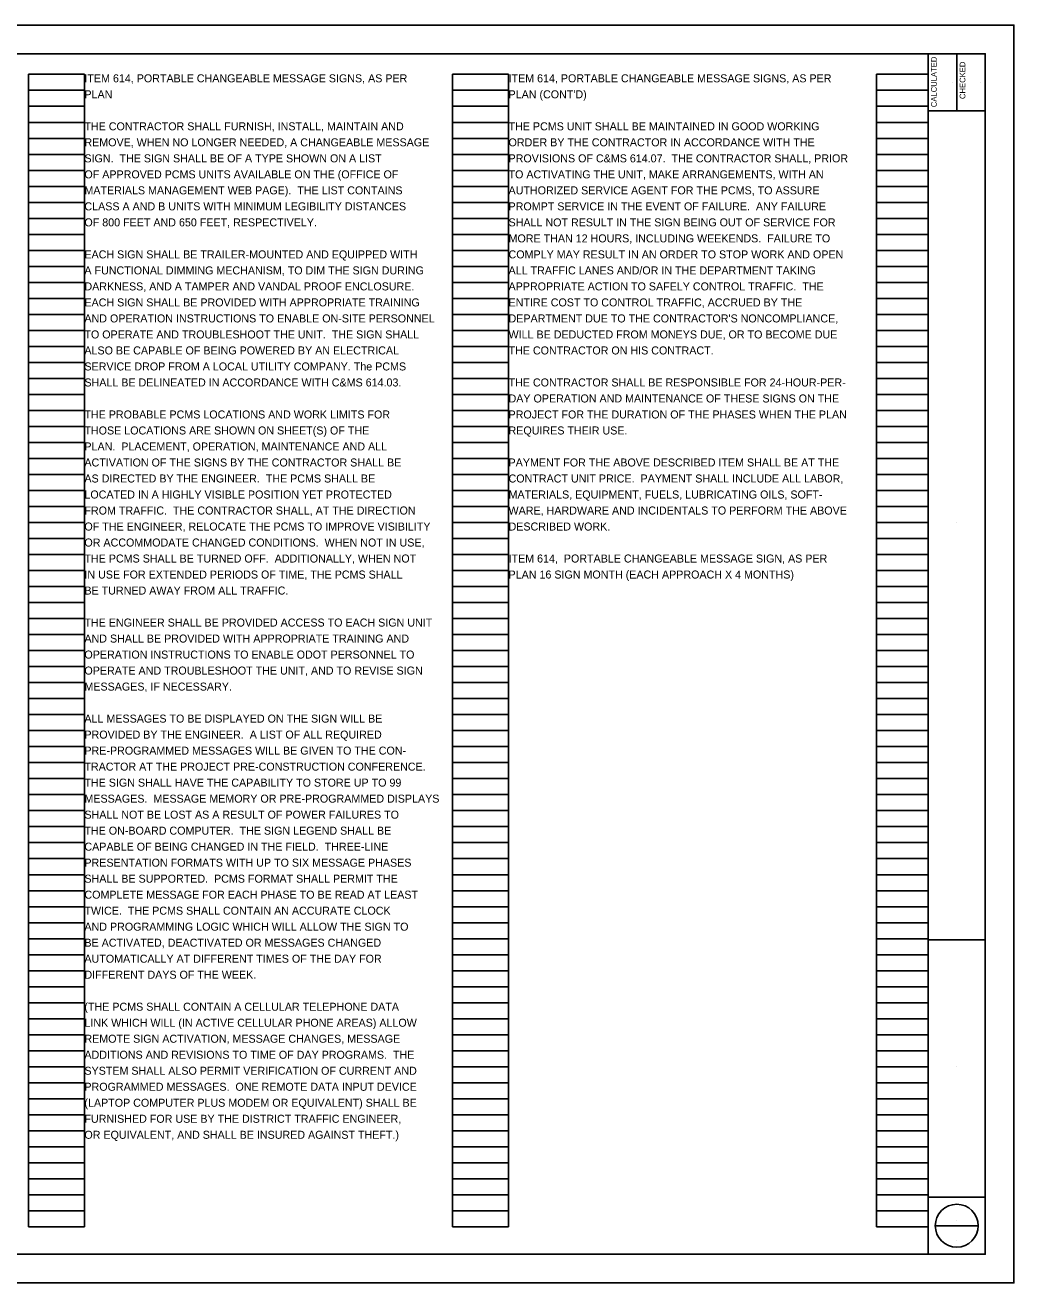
# Model space of a CAD drawing. Extents: x 0 to 71.8, y 0 to 22.
# Drawn here: x 16.7 to 34, y 0 to 22 of the extents above; entities that cross this region are included whole.
import ezdxf

# ---------------------------------------------------------------- set-up
doc = ezdxf.new("R2010")
doc.units = 0
for name, color, linetype in [('MT_P_Work_Area', 7, 'Continuous'), ('SH_Cut_Line', 7, 'Continuous'), ('SH_Data', 7, 'Continuous'), ('SH_Text', 7, 'Continuous')]:
    doc.layers.add(name, color=color, linetype=linetype)

msp = doc.modelspace()

# ---------------------------------------------------------------- linework, layer by layer
at = {"layer": 'MT_P_Work_Area'}
for p, q in [((32.5, 0.5), (32.5, 21.5)), ((33, 21.5), (33, 20.5)), ((32.5, 20.5), (33.5, 20.5)), ((32.5, 6), (33.5, 6)), ((32.5, 1.5), (33.5, 1.5))]:
    msp.add_line(p, q, dxfattribs=at)
msp.add_lwpolyline([(2, 21.5), (33.5, 21.5), (33.5, 0.5), (2, 0.5)], close=True, dxfattribs=at)
at = {"layer": 'SH_Cut_Line'}
msp.add_lwpolyline([(0, 0), (34, 0), (34, 22), (0, 22)], close=True, dxfattribs=at)
at = {"layer": 'SH_Data'}
for p, q in [((16.76, 0.98), (16.76, 21.14)), ((16.76, 21.14), (17.74, 21.14)), ((17.74, 0.98), (17.74, 21.14)), ((24.18, 0.98), (24.18, 21.14)), ((24.18, 21.14), (25.16, 21.14)), ((25.16, 0.98), (25.16, 21.14)), ((31.6, 0.98), (31.6, 21.14)), ((31.6, 21.14), (32.5, 21.14)), ((32.5, 0.98), (32.5, 21.14)), ((32.92, 21.004), (32.92, 21.004)), ((33.42, 21.004), (33.42, 21.004)), ((16.76, 20.86), (17.74, 20.86)), ((24.18, 20.86), (25.16, 20.86)), ((31.6, 20.86), (32.5, 20.86)), ((16.76, 20.58), (17.74, 20.58)), ((24.18, 20.58), (25.16, 20.58)), ((31.6, 20.58), (32.5, 20.58)), ((16.76, 20.3), (17.74, 20.3)), ((24.18, 20.3), (25.16, 20.3)), ((31.6, 20.3), (32.5, 20.3)), ((16.76, 20.02), (17.74, 20.02)), ((24.18, 20.02), (25.16, 20.02)), ((31.6, 20.02), (32.5, 20.02)), ((16.76, 19.74), (17.74, 19.74)), ((24.18, 19.74), (25.16, 19.74)), ((31.6, 19.74), (32.5, 19.74)), ((16.76, 19.46), (17.74, 19.46)), ((24.18, 19.46), (25.16, 19.46)), ((31.6, 19.46), (32.5, 19.46)), ((16.76, 19.18), (17.74, 19.18)), ((24.18, 19.18), (25.16, 19.18)), ((31.6, 19.18), (32.5, 19.18)), ((16.76, 18.9), (17.74, 18.9)), ((24.18, 18.9), (25.16, 18.9)), ((31.6, 18.9), (32.5, 18.9)), ((16.76, 18.62), (17.74, 18.62)), ((24.18, 18.62), (25.16, 18.62)), ((31.6, 18.62), (32.5, 18.62)), ((16.76, 18.34), (17.74, 18.34)), ((24.18, 18.34), (25.16, 18.34)), ((31.6, 18.34), (32.5, 18.34)), ((16.76, 18.06), (17.74, 18.06)), ((24.18, 18.06), (25.16, 18.06)), ((31.6, 18.06), (32.5, 18.06)), ((16.76, 17.78), (17.74, 17.78)), ((24.18, 17.78), (25.16, 17.78)), ((31.6, 17.78), (32.5, 17.78)), ((16.76, 17.5), (17.74, 17.5)), ((24.18, 17.5), (25.16, 17.5)), ((31.6, 17.5), (32.5, 17.5)), ((16.76, 17.22), (17.74, 17.22)), ((24.18, 17.22), (25.16, 17.22)), ((31.6, 17.22), (32.5, 17.22)), ((16.76, 16.94), (17.74, 16.94)), ((24.18, 16.94), (25.16, 16.94)), ((31.6, 16.94), (32.5, 16.94)), ((16.76, 16.66), (17.74, 16.66)), ((24.18, 16.66), (25.16, 16.66)), ((31.6, 16.66), (32.5, 16.66)), ((16.76, 16.38), (17.74, 16.38)), ((24.18, 16.38), (25.16, 16.38)), ((31.6, 16.38), (32.5, 16.38)), ((16.76, 16.1), (17.74, 16.1)), ((24.18, 16.1), (25.16, 16.1)), ((31.6, 16.1), (32.5, 16.1)), ((16.76, 15.82), (17.74, 15.82)), ((24.18, 15.82), (25.16, 15.82)), ((31.6, 15.82), (32.5, 15.82)), ((16.76, 15.54), (17.74, 15.54)), ((24.18, 15.54), (25.16, 15.54)), ((31.6, 15.54), (32.5, 15.54)), ((16.76, 15.26), (17.74, 15.26)), ((24.18, 15.26), (25.16, 15.26)), ((31.6, 15.26), (32.5, 15.26)), ((16.76, 14.98), (17.74, 14.98)), ((24.18, 14.98), (25.16, 14.98)), ((31.6, 14.98), (32.5, 14.98)), ((16.76, 14.7), (17.74, 14.7)), ((24.18, 14.7), (25.16, 14.7)), ((31.6, 14.7), (32.5, 14.7)), ((16.76, 14.42), (17.74, 14.42)), ((24.18, 14.42), (25.16, 14.42)), ((31.6, 14.42), (32.5, 14.42)), ((16.76, 14.14), (17.74, 14.14)), ((24.18, 14.14), (25.16, 14.14)), ((31.6, 14.14), (32.5, 14.14)), ((16.76, 13.86), (17.74, 13.86)), ((24.18, 13.86), (25.16, 13.86)), ((31.6, 13.86), (32.5, 13.86)), ((16.76, 13.58), (17.74, 13.58)), ((24.18, 13.58), (25.16, 13.58)), ((31.6, 13.58), (32.5, 13.58)), ((16.76, 13.3), (17.74, 13.3)), ((24.18, 13.3), (25.16, 13.3)), ((31.6, 13.3), (32.5, 13.3)), ((33, 13.292), (33, 13.292)), ((16.76, 13.02), (17.74, 13.02)), ((24.18, 13.02), (25.16, 13.02)), ((31.6, 13.02), (32.5, 13.02)), ((16.76, 12.74), (17.74, 12.74)), ((24.18, 12.74), (25.16, 12.74)), ((31.6, 12.74), (32.5, 12.74)), ((16.76, 12.46), (17.74, 12.46)), ((24.18, 12.46), (25.16, 12.46)), ((31.6, 12.46), (32.5, 12.46)), ((16.76, 12.18), (17.74, 12.18)), ((24.18, 12.18), (25.16, 12.18)), ((31.6, 12.18), (32.5, 12.18)), ((16.76, 11.9), (17.74, 11.9)), ((24.18, 11.9), (25.16, 11.9)), ((31.6, 11.9), (32.5, 11.9)), ((16.76, 11.62), (17.74, 11.62)), ((24.18, 11.62), (25.16, 11.62)), ((31.6, 11.62), (32.5, 11.62)), ((16.76, 11.34), (17.74, 11.34)), ((24.18, 11.34), (25.16, 11.34)), ((31.6, 11.34), (32.5, 11.34)), ((16.76, 11.06), (17.74, 11.06)), ((24.18, 11.06), (25.16, 11.06)), ((31.6, 11.06), (32.5, 11.06)), ((16.76, 10.78), (17.74, 10.78)), ((24.18, 10.78), (25.16, 10.78)), ((31.6, 10.78), (32.5, 10.78)), ((16.76, 10.5), (17.74, 10.5)), ((24.18, 10.5), (25.16, 10.5)), ((31.6, 10.5), (32.5, 10.5)), ((16.76, 10.22), (17.74, 10.22)), ((24.18, 10.22), (25.16, 10.22)), ((31.6, 10.22), (32.5, 10.22)), ((16.76, 9.94), (17.74, 9.94)), ((24.18, 9.94), (25.16, 9.94)), ((31.6, 9.94), (32.5, 9.94)), ((16.76, 9.66), (17.74, 9.66)), ((24.18, 9.66), (25.16, 9.66)), ((31.6, 9.66), (32.5, 9.66)), ((16.76, 9.38), (17.74, 9.38)), ((24.18, 9.38), (25.16, 9.38)), ((31.6, 9.38), (32.5, 9.38)), ((16.76, 9.1), (17.74, 9.1)), ((24.18, 9.1), (25.16, 9.1)), ((31.6, 9.1), (32.5, 9.1)), ((16.76, 8.82), (17.74, 8.82)), ((24.18, 8.82), (25.16, 8.82)), ((31.6, 8.82), (32.5, 8.82)), ((16.76, 8.54), (17.74, 8.54)), ((24.18, 8.54), (25.16, 8.54)), ((31.6, 8.54), (32.5, 8.54)), ((16.76, 8.26), (17.74, 8.26)), ((24.18, 8.26), (25.16, 8.26)), ((31.6, 8.26), (32.5, 8.26)), ((16.76, 7.98), (17.74, 7.98)), ((24.18, 7.98), (25.16, 7.98)), ((31.6, 7.98), (32.5, 7.98)), ((16.76, 7.7), (17.74, 7.7)), ((24.18, 7.7), (25.16, 7.7)), ((31.6, 7.7), (32.5, 7.7)), ((16.76, 7.42), (17.74, 7.42)), ((24.18, 7.42), (25.16, 7.42)), ((31.6, 7.42), (32.5, 7.42)), ((16.76, 7.14), (17.74, 7.14)), ((24.18, 7.14), (25.16, 7.14)), ((31.6, 7.14), (32.5, 7.14)), ((16.76, 6.86), (17.74, 6.86)), ((24.18, 6.86), (25.16, 6.86)), ((31.6, 6.86), (32.5, 6.86)), ((16.76, 6.58), (17.74, 6.58)), ((24.18, 6.58), (25.16, 6.58)), ((31.6, 6.58), (32.5, 6.58)), ((16.76, 6.3), (17.74, 6.3)), ((24.18, 6.3), (25.16, 6.3)), ((31.6, 6.3), (32.5, 6.3)), ((16.76, 6.02), (17.74, 6.02)), ((24.18, 6.02), (25.16, 6.02)), ((31.6, 6.02), (32.5, 6.02)), ((16.76, 5.74), (17.74, 5.74)), ((24.18, 5.74), (25.16, 5.74)), ((31.6, 5.74), (32.5, 5.74)), ((16.76, 5.46), (17.74, 5.46)), ((24.18, 5.46), (25.16, 5.46)), ((31.6, 5.46), (32.5, 5.46)), ((16.76, 5.18), (17.74, 5.18)), ((24.18, 5.18), (25.16, 5.18)), ((31.6, 5.18), (32.5, 5.18)), ((16.76, 4.9), (17.74, 4.9)), ((24.18, 4.9), (25.16, 4.9)), ((31.6, 4.9), (32.5, 4.9)), ((16.76, 4.62), (17.74, 4.62)), ((24.18, 4.62), (25.16, 4.62)), ((31.6, 4.62), (32.5, 4.62)), ((16.76, 4.34), (17.74, 4.34)), ((24.18, 4.34), (25.16, 4.34)), ((31.6, 4.34), (32.5, 4.34)), ((16.76, 4.06), (17.74, 4.06)), ((24.18, 4.06), (25.16, 4.06)), ((31.6, 4.06), (32.5, 4.06)), ((16.76, 3.78), (17.74, 3.78)), ((24.18, 3.78), (25.16, 3.78)), ((31.6, 3.78), (32.5, 3.78)), ((33, 3.792), (33, 3.792)), ((16.76, 3.5), (17.74, 3.5)), ((24.18, 3.5), (25.16, 3.5)), ((31.6, 3.5), (32.5, 3.5)), ((16.76, 3.22), (17.74, 3.22)), ((24.18, 3.22), (25.16, 3.22)), ((31.6, 3.22), (32.5, 3.22)), ((16.76, 2.94), (17.74, 2.94)), ((24.18, 2.94), (25.16, 2.94)), ((31.6, 2.94), (32.5, 2.94)), ((16.76, 2.66), (17.74, 2.66)), ((24.18, 2.66), (25.16, 2.66)), ((31.6, 2.66), (32.5, 2.66)), ((16.76, 2.38), (17.74, 2.38)), ((24.18, 2.38), (25.16, 2.38)), ((31.6, 2.38), (32.5, 2.38)), ((16.76, 2.1), (17.74, 2.1)), ((24.18, 2.1), (25.16, 2.1)), ((31.6, 2.1), (32.5, 2.1)), ((16.76, 1.82), (17.74, 1.82)), ((24.18, 1.82), (25.16, 1.82)), ((31.6, 1.82), (32.5, 1.82)), ((16.76, 1.54), (17.74, 1.54)), ((24.18, 1.54), (25.16, 1.54)), ((31.6, 1.54), (32.5, 1.54)), ((16.76, 1.26), (17.74, 1.26)), ((24.18, 1.26), (25.16, 1.26)), ((31.6, 1.26), (32.5, 1.26)), ((16.76, 0.98), (17.74, 0.98)), ((24.18, 0.98), (25.16, 0.98)), ((31.6, 0.98), (32.5, 0.98)), ((32.625, 1), (33.375, 1)), ((33, 1.085), (33, 1.085)), ((33, 0.745), (33, 0.745))]:
    msp.add_line(p, q, dxfattribs=at)
msp.add_circle((33, 1), 0.375, dxfattribs=at)

# ---------------------------------------------------------------- texts
for s, p in [('CALCULATED', (32.652, 20.565)), ('CHECKED', (33.152, 20.708))]:
    msp.add_text(s, height=0.1, rotation=90, dxfattribs=at).set_placement(p)
at = {"layer": 'SH_Text'}
for s, p in [('ITEM 614, PORTABLE CHANGEABLE MESSAGE SIGNS, AS PER', (17.74, 21)), ('ITEM 614, PORTABLE CHANGEABLE MESSAGE SIGNS, AS PER', (25.16, 21)), ('PLAN', (17.74, 20.72)), ("PLAN (CONT'D)", (25.16, 20.72)), ('THE CONTRACTOR SHALL FURNISH, INSTALL, MAINTAIN AND', (17.74, 20.16)), ('THE PCMS UNIT SHALL BE MAINTAINED IN GOOD WORKING', (25.16, 20.16)), ('REMOVE, WHEN NO LONGER NEEDED, A CHANGEABLE MESSAGE', (17.74, 19.88)), ('ORDER BY THE CONTRACTOR IN ACCORDANCE WITH THE', (25.16, 19.88)), ('SIGN.  THE SIGN SHALL BE OF A TYPE SHOWN ON A LIST', (17.74, 19.6)), ('PROVISIONS OF C&MS 614.07.  THE CONTRACTOR SHALL, PRIOR', (25.16, 19.6)), ('OF APPROVED PCMS UNITS AVAILABLE ON THE (OFFICE OF', (17.74, 19.32)), ('TO ACTIVATING THE UNIT, MAKE ARRANGEMENTS, WITH AN', (25.16, 19.32)), ('MATERIALS MANAGEMENT WEB PAGE).  THE LIST CONTAINS', (17.74, 19.04)), ('AUTHORIZED SERVICE AGENT FOR THE PCMS, TO ASSURE', (25.16, 19.04)), ('CLASS A AND B UNITS WITH MINIMUM LEGIBILITY DISTANCES', (17.74, 18.76)), ('PROMPT SERVICE IN THE EVENT OF FAILURE.  ANY FAILURE', (25.16, 18.76)), ('OF 800 FEET AND 650 FEET, RESPECTIVELY.', (17.74, 18.48)), ('SHALL NOT RESULT IN THE SIGN BEING OUT OF SERVICE FOR', (25.16, 18.48)), ('MORE THAN 12 HOURS, INCLUDING WEEKENDS.  FAILURE TO', (25.16, 18.2)), ('EACH SIGN SHALL BE TRAILER-MOUNTED AND EQUIPPED WITH', (17.74, 17.92)), ('COMPLY MAY RESULT IN AN ORDER TO STOP WORK AND OPEN', (25.16, 17.92)), ('A FUNCTIONAL DIMMING MECHANISM, TO DIM THE SIGN DURING', (17.74, 17.64)), ('ALL TRAFFIC LANES AND/OR IN THE DEPARTMENT TAKING', (25.16, 17.64)), ('DARKNESS, AND A TAMPER AND VANDAL PROOF ENCLOSURE.', (17.74, 17.36)), ('APPROPRIATE ACTION TO SAFELY CONTROL TRAFFIC.  THE', (25.16, 17.36)), ('EACH SIGN SHALL BE PROVIDED WITH APPROPRIATE TRAINING', (17.74, 17.08)), ('ENTIRE COST TO CONTROL TRAFFIC, ACCRUED BY THE', (25.16, 17.08)), ('AND OPERATION INSTRUCTIONS TO ENABLE ON-SITE PERSONNEL', (17.74, 16.8)), ("DEPARTMENT DUE TO THE CONTRACTOR'S NONCOMPLIANCE,", (25.16, 16.8)), ('TO OPERATE AND TROUBLESHOOT THE UNIT.  THE SIGN SHALL', (17.74, 16.52)), ('WILL BE DEDUCTED FROM MONEYS DUE, OR TO BECOME DUE', (25.16, 16.52)), ('ALSO BE CAPABLE OF BEING POWERED BY AN ELECTRICAL', (17.74, 16.24)), ('THE CONTRACTOR ON HIS CONTRACT.', (25.16, 16.24)), ('SERVICE DROP FROM A LOCAL UTILITY COMPANY. The PCMS', (17.74, 15.96)), ('SHALL BE DELINEATED IN ACCORDANCE WITH C&MS 614.03.', (17.74, 15.68)), ('THE CONTRACTOR SHALL BE RESPONSIBLE FOR 24-HOUR-PER-', (25.16, 15.68)), ('DAY OPERATION AND MAINTENANCE OF THESE SIGNS ON THE', (25.16, 15.4)), ('THE PROBABLE PCMS LOCATIONS AND WORK LIMITS FOR', (17.74, 15.12)), ('PROJECT FOR THE DURATION OF THE PHASES WHEN THE PLAN', (25.16, 15.12)), ('THOSE LOCATIONS ARE SHOWN ON SHEET(S) OF THE', (17.74, 14.84)), ('REQUIRES THEIR USE.', (25.16, 14.84)), ('PLAN.  PLACEMENT, OPERATION, MAINTENANCE AND ALL', (17.74, 14.56)), ('ACTIVATION OF THE SIGNS BY THE CONTRACTOR SHALL BE', (17.74, 14.28)), ('PAYMENT FOR THE ABOVE DESCRIBED ITEM SHALL BE AT THE', (25.16, 14.28)), ('AS DIRECTED BY THE ENGINEER.  THE PCMS SHALL BE', (17.74, 14)), ('CONTRACT UNIT PRICE.  PAYMENT SHALL INCLUDE ALL LABOR,', (25.16, 14)), ('LOCATED IN A HIGHLY VISIBLE POSITION YET PROTECTED', (17.74, 13.72)), ('MATERIALS, EQUIPMENT, FUELS, LUBRICATING OILS, SOFT-', (25.16, 13.72)), ('FROM TRAFFIC.  THE CONTRACTOR SHALL, AT THE DIRECTION', (17.74, 13.44)), ('WARE, HARDWARE AND INCIDENTALS TO PERFORM THE ABOVE', (25.16, 13.44)), ('OF THE ENGINEER, RELOCATE THE PCMS TO IMPROVE VISIBILITY', (17.74, 13.16)), ('DESCRIBED WORK.', (25.16, 13.16)), ('OR ACCOMMODATE CHANGED CONDITIONS.  WHEN NOT IN USE,', (17.74, 12.88)), ('THE PCMS SHALL BE TURNED OFF.  ADDITIONALLY, WHEN NOT', (17.74, 12.6)), ('ITEM 614,  PORTABLE CHANGEABLE MESSAGE SIGN, AS PER', (25.16, 12.6)), ('IN USE FOR EXTENDED PERIODS OF TIME, THE PCMS SHALL', (17.74, 12.32)), ('PLAN 16 SIGN MONTH (EACH APPROACH X 4 MONTHS)', (25.16, 12.32)), ('BE TURNED AWAY FROM ALL TRAFFIC.', (17.74, 12.04)), ('THE ENGINEER SHALL BE PROVIDED ACCESS TO EACH SIGN UNIT', (17.74, 11.48)), ('AND SHALL BE PROVIDED WITH APPROPRIATE TRAINING AND', (17.74, 11.2)), ('OPERATION INSTRUCTIONS TO ENABLE ODOT PERSONNEL TO', (17.74, 10.92)), ('OPERATE AND TROUBLESHOOT THE UNIT, AND TO REVISE SIGN', (17.74, 10.64)), ('MESSAGES, IF NECESSARY.', (17.74, 10.36)), ('ALL MESSAGES TO BE DISPLAYED ON THE SIGN WILL BE', (17.74, 9.8)), ('PROVIDED BY THE ENGINEER.  A LIST OF ALL REQUIRED', (17.74, 9.52)), ('PRE-PROGRAMMED MESSAGES WILL BE GIVEN TO THE CON-', (17.74, 9.24)), ('TRACTOR AT THE PROJECT PRE-CONSTRUCTION CONFERENCE.', (17.74, 8.96)), ('THE SIGN SHALL HAVE THE CAPABILITY TO STORE UP TO 99', (17.74, 8.68)), ('MESSAGES.  MESSAGE MEMORY OR PRE-PROGRAMMED DISPLAYS', (17.74, 8.4)), ('SHALL NOT BE LOST AS A RESULT OF POWER FAILURES TO', (17.74, 8.12)), ('THE ON-BOARD COMPUTER.  THE SIGN LEGEND SHALL BE', (17.74, 7.84)), ('CAPABLE OF BEING CHANGED IN THE FIELD.  THREE-LINE', (17.74, 7.56)), ('PRESENTATION FORMATS WITH UP TO SIX MESSAGE PHASES', (17.74, 7.28)), ('SHALL BE SUPPORTED.  PCMS FORMAT SHALL PERMIT THE', (17.74, 7)), ('COMPLETE MESSAGE FOR EACH PHASE TO BE READ AT LEAST', (17.74, 6.72)), ('TWICE.  THE PCMS SHALL CONTAIN AN ACCURATE CLOCK', (17.74, 6.44)), ('AND PROGRAMMING LOGIC WHICH WILL ALLOW THE SIGN TO', (17.74, 6.16)), ('BE ACTIVATED, DEACTIVATED OR MESSAGES CHANGED', (17.74, 5.88)), ('AUTOMATICALLY AT DIFFERENT TIMES OF THE DAY FOR', (17.74, 5.6)), ('DIFFERENT DAYS OF THE WEEK.', (17.74, 5.32)), ('(THE PCMS SHALL CONTAIN A CELLULAR TELEPHONE DATA', (17.74, 4.76)), ('LINK WHICH WILL (IN ACTIVE CELLULAR PHONE AREAS) ALLOW', (17.74, 4.48)), ('REMOTE SIGN ACTIVATION, MESSAGE CHANGES, MESSAGE', (17.74, 4.2)), ('ADDITIONS AND REVISIONS TO TIME OF DAY PROGRAMS.  THE', (17.74, 3.92)), ('SYSTEM SHALL ALSO PERMIT VERIFICATION OF CURRENT AND', (17.74, 3.64)), ('PROGRAMMED MESSAGES.  ONE REMOTE DATA INPUT DEVICE', (17.74, 3.36)), ('(LAPTOP COMPUTER PLUS MODEM OR EQUIVALENT) SHALL BE', (17.74, 3.08)), ('FURNISHED FOR USE BY THE DISTRICT TRAFFIC ENGINEER,', (17.74, 2.8)), ('OR EQUIVALENT, AND SHALL BE INSURED AGAINST THEFT.)', (17.74, 2.52))]:
    msp.add_text(s, height=0.14, dxfattribs=at).set_placement(p)

doc.saveas('drawing.dxf')
